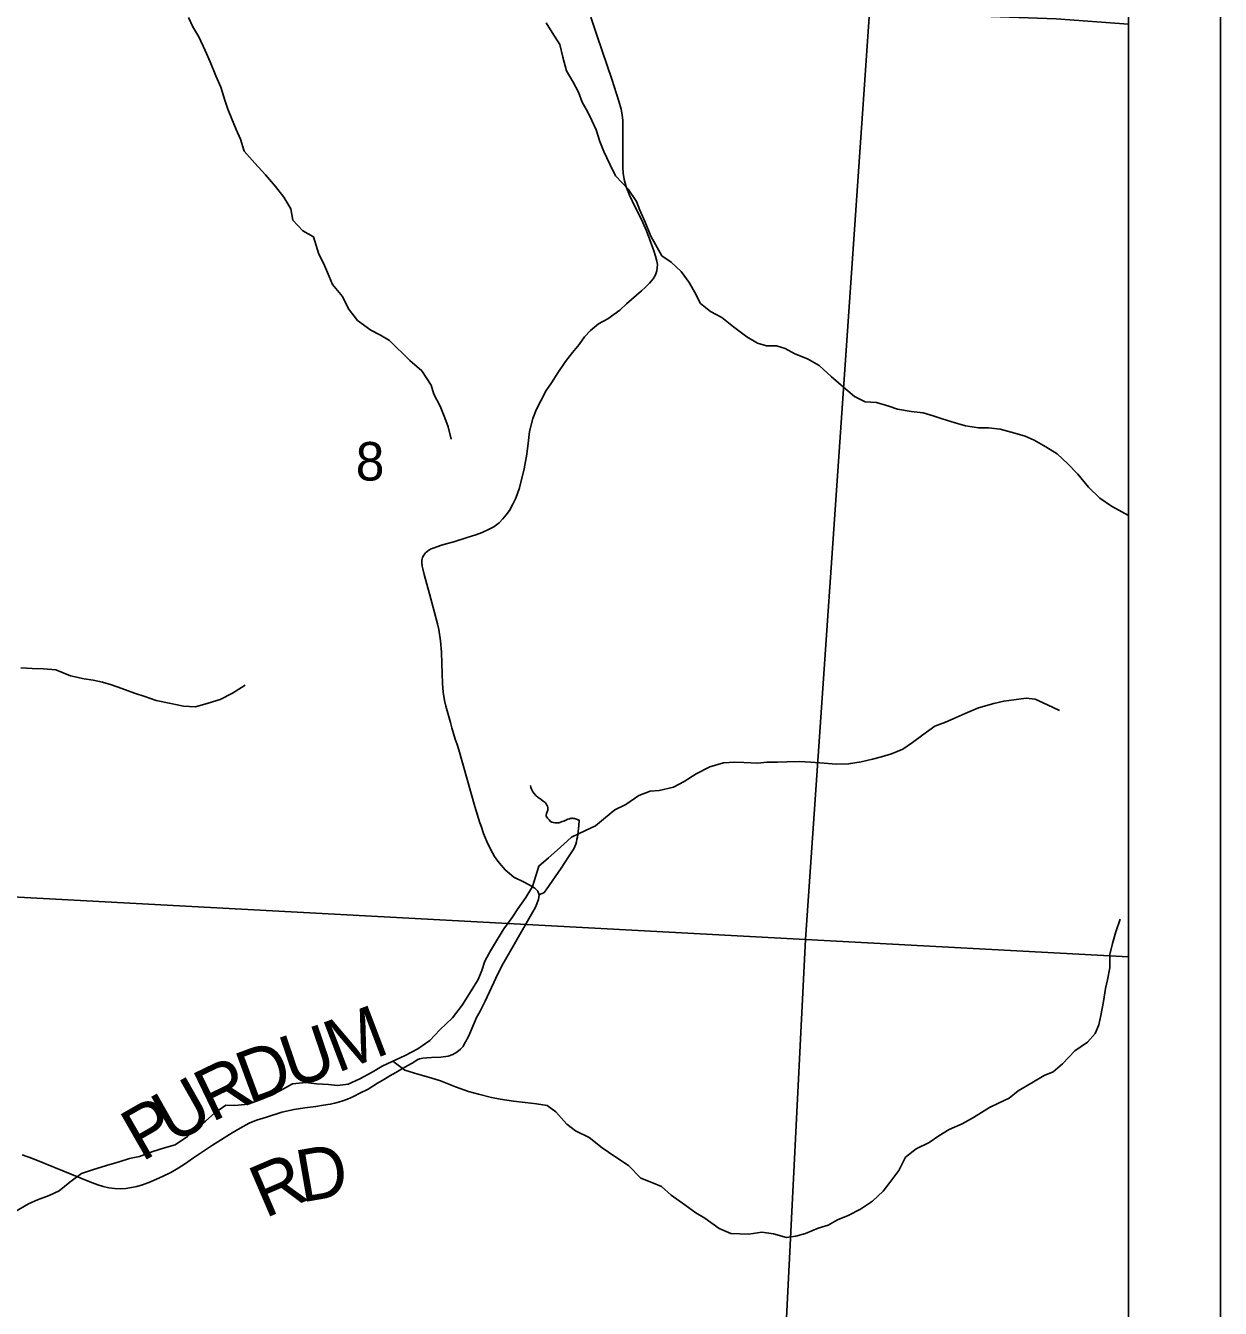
# Model space of a CAD drawing. Extents: x 39.8 to 73.8, y 13 to 35.
# Drawn here: x 47.463 to 48.763, y 28.456 to 29.851 of the extents above; entities that cross this region are included whole.
import ezdxf

# ---------------------------------------------------------------- set-up
doc = ezdxf.new("R2010")
doc.units = 0
for name, color, linetype in [('GM_X_Corporation', 7, 'Continuous'), ('GM_X_Minor_River', 7, 'Continuous'), ('GM_X_Section_Text', 7, 'Continuous'), ('GM_X_Township_Road', 7, 'Continuous'), ('GM_X_Township_Road_Text', 7, 'Continuous'), ('SH_Data', 7, 'Continuous')]:
    doc.layers.add(name, color=color, linetype=linetype)

msp = doc.modelspace()

# ---------------------------------------------------------------- linework, layer by layer
at = {"layer": 'GM_X_Corporation'}
msp.add_lwpolyline([(47.095, 27.8783), (47.5149, 27.8498), (47.5414, 27.8484), (48.663, 27.7809), (48.663, 33.865), (43.6158, 33.865)], dxfattribs=at)
for points in [[(47.3645, 29.9274), (47.3755, 29.9267), (47.6104, 29.9124), (48.0851, 29.8835), (48.3814, 29.8655), (48.3118, 28.8573), (47.3001, 28.9116)], [(48.663, 28.8384), (48.663, 29.8523), (48.5842, 29.8582), (48.3814, 29.8655), (48.3118, 28.8573)], [(47.3001, 28.9116), (48.3118, 28.8573), (48.2586, 27.803), (47.2222, 27.869), (47.3019, 28.7918)], [(48.663, 27.7774), (48.663, 28.8384), (48.3118, 28.8573), (48.2586, 27.803)]]:
    msp.add_lwpolyline(points, close=True, dxfattribs=at)
at = {"layer": 'GM_X_Minor_River'}
for p, q in [((47.6403, 29.8596), (47.6453, 29.8494)), ((47.6453, 29.8494), (47.6518, 29.8388)), ((47.6518, 29.8388), (47.6587, 29.824)), ((47.6587, 29.824), (47.664, 29.8115)), ((47.664, 29.8115), (47.6701, 29.7964)), ((47.6701, 29.7964), (47.6755, 29.7839)), ((47.6755, 29.7839), (47.6801, 29.7698)), ((47.6801, 29.7698), (47.6832, 29.76)), ((47.6832, 29.76), (47.6874, 29.7501)), ((47.6874, 29.7501), (47.6924, 29.738)), ((47.6924, 29.738), (47.697, 29.7274)), ((47.697, 29.7274), (47.7012, 29.7145)), ((47.7012, 29.7145), (47.7126, 29.7013)), ((47.7126, 29.7013), (47.7244, 29.6888)), ((47.7244, 29.6888), (47.735, 29.6759)), ((47.735, 29.6759), (47.7442, 29.6642)), ((47.7442, 29.6642), (47.7518, 29.6517)), ((47.7518, 29.6517), (47.7538, 29.6392)), ((47.7538, 29.6392), (47.7648, 29.6279)), ((47.7648, 29.6279), (47.7763, 29.6212)), ((47.7763, 29.6212), (47.7823, 29.6025)), ((48.1435, 29.622), (48.1554, 29.6006)), ((47.7823, 29.6025), (47.7873, 29.5927)), ((48.1554, 29.6006), (48.1657, 29.5935)), ((47.7873, 29.5927), (47.7916, 29.5825)), ((48.1657, 29.5935), (48.1764, 29.5837)), ((47.7916, 29.5825), (47.797, 29.5693)), ((48.1764, 29.5837), (48.1852, 29.5717)), ((48.1852, 29.5717), (48.191, 29.5615)), ((47.797, 29.5693), (47.8081, 29.5565)), ((47.8081, 29.5565), (47.8146, 29.5429)), ((48.191, 29.5615), (48.1975, 29.5487)), ((47.8146, 29.5429), (47.8242, 29.5301)), ((48.1975, 29.5487), (48.2082, 29.5401)), ((47.8242, 29.5301), (47.8387, 29.5196)), ((48.2082, 29.5401), (48.2207, 29.5334)), ((48.2207, 29.5334), (48.2333, 29.5232)), ((47.8387, 29.5196), (47.8493, 29.5144)), ((48.2333, 29.5232), (48.2478, 29.5124)), ((47.8493, 29.5144), (47.8592, 29.5085)), ((47.8592, 29.5085), (47.8813, 29.4867)), ((48.2478, 29.5124), (48.2595, 29.5057)), ((48.2595, 29.5057), (48.2694, 29.5027)), ((48.2694, 29.5027), (48.28, 29.5028)), ((48.28, 29.5028), (48.2895, 29.4999)), ((48.2895, 29.4999), (48.3001, 29.4939)), ((48.3001, 29.4939), (48.3138, 29.4887)), ((48.3138, 29.4887), (48.3267, 29.4813)), ((47.8813, 29.4867), (47.8943, 29.4754)), ((47.8943, 29.4754), (47.9043, 29.46)), ((48.3267, 29.4813), (48.3397, 29.4693)), ((47.9043, 29.46), (47.9074, 29.4502)), ((48.3397, 29.4693), (48.353, 29.4576)), ((47.9074, 29.4502), (47.9143, 29.437)), ((48.353, 29.4576), (48.3649, 29.4475)), ((48.3649, 29.4475), (48.3766, 29.4419)), ((47.9143, 29.437), (47.9193, 29.4245)), ((48.3766, 29.4419), (48.3888, 29.4409)), ((48.3888, 29.4409), (48.4024, 29.4372)), ((48.4024, 29.4372), (48.4119, 29.4339)), ((48.4119, 29.4339), (48.4267, 29.4314)), ((48.4267, 29.4314), (48.4396, 29.43)), ((47.9193, 29.4245), (47.9228, 29.4147)), ((48.4396, 29.43), (48.4506, 29.4267)), ((48.4506, 29.4267), (48.4604, 29.4234)), ((48.4604, 29.4234), (48.4745, 29.4189)), ((48.4745, 29.4189), (48.4858, 29.4156)), ((47.9228, 29.4147), (47.9263, 29.4011)), ((48.4858, 29.4156), (48.4999, 29.4135)), ((48.4999, 29.4135), (48.5108, 29.4136)), ((48.5108, 29.4136), (48.5233, 29.4122)), ((48.5233, 29.4122), (48.5393, 29.4078)), ((48.5393, 29.4078), (48.5506, 29.4045)), ((48.5506, 29.4045), (48.5605, 29.4)), ((48.5605, 29.4), (48.5731, 29.3929)), ((48.5731, 29.3929), (48.5856, 29.3851)), ((48.5856, 29.3851), (48.5971, 29.3742)), ((48.5971, 29.3742), (48.6081, 29.3633)), ((48.6081, 29.3633), (48.6196, 29.349)), ((48.6196, 29.349), (48.6318, 29.337)), ((48.6318, 29.337), (48.6444, 29.3284)), ((48.6444, 29.3284), (48.6558, 29.3221)), ((48.6558, 29.3221), (48.663, 29.3182)), ((47.4582, 29.1524), (47.4703, 29.1517)), ((47.4703, 29.1517), (47.4828, 29.1515)), ((47.4828, 29.1515), (47.496, 29.1504)), ((47.496, 29.1504), (47.512, 29.1438)), ((47.512, 29.1438), (47.5268, 29.1405)), ((47.5268, 29.1405), (47.5366, 29.1391)), ((47.5366, 29.1391), (47.5469, 29.1369)), ((47.5469, 29.1369), (47.5567, 29.1339)), ((47.5567, 29.1339), (47.5681, 29.1299)), ((47.5681, 29.1299), (47.5818, 29.1251)), ((47.5818, 29.1251), (47.5928, 29.1214)), ((47.6749, 29.118), (47.6885, 29.1249)), ((47.6885, 29.1249), (47.702, 29.1338)), ((47.5928, 29.1214), (47.6053, 29.117)), ((47.6053, 29.117), (47.6212, 29.1137)), ((47.6212, 29.1137), (47.6349, 29.1108)), ((47.6349, 29.1108), (47.6481, 29.1101)), ((47.6481, 29.1101), (47.6617, 29.1141)), ((47.6617, 29.1141), (47.6749, 29.118)), ((48.6492, 28.8654), (48.654, 28.8794)), ((48.6455, 28.8528), (48.6492, 28.8654)), ((48.6429, 28.8407), (48.6455, 28.8528)), ((48.6427, 28.8263), (48.6429, 28.8407)), ((48.6402, 28.8134), (48.6427, 28.8263)), ((48.6358, 28.7898), (48.638, 28.8039)), ((48.638, 28.8039), (48.6402, 28.8134)), ((48.6329, 28.7743), (48.6358, 28.7898)), ((48.6267, 28.7549), (48.6307, 28.7644)), ((48.6307, 28.7644), (48.6329, 28.7743)), ((48.6184, 28.7454), (48.6267, 28.7549)), ((48.5914, 28.722), (48.6045, 28.7361)), ((48.6045, 28.7361), (48.6184, 28.7454)), ((47.8627, 28.7248), (47.8759, 28.7151)), ((48.5812, 28.7132), (48.5914, 28.722)), ((47.8759, 28.7151), (47.89, 28.7107)), ((47.89, 28.7107), (47.904, 28.7066)), ((47.904, 28.7066), (47.9146, 28.7033)), ((48.5579, 28.7012), (48.5714, 28.7093)), ((48.5714, 28.7093), (48.5812, 28.7132)), ((47.9146, 28.7033), (47.931, 28.697)), ((47.931, 28.697), (47.945, 28.6918)), ((47.945, 28.6918), (47.956, 28.6889)), ((48.5331, 28.6847), (48.5432, 28.6924)), ((48.5432, 28.6924), (48.5579, 28.7012)), ((47.956, 28.6889), (47.97, 28.6853)), ((47.97, 28.6853), (47.9795, 28.6834)), ((47.9795, 28.6834), (47.9939, 28.6813)), ((47.9939, 28.6813), (48.0068, 28.6799)), ((48.0068, 28.6799), (48.0189, 28.6785)), ((48.0189, 28.6785), (48.0307, 28.6767)), ((48.512, 28.6743), (48.5218, 28.6793)), ((48.5218, 28.6793), (48.5331, 28.6847)), ((48.0307, 28.6767), (48.0402, 28.6696)), ((48.0402, 28.6696), (48.052, 28.6564)), ((48.4943, 28.6635), (48.512, 28.6743)), ((48.052, 28.6564), (48.0615, 28.649)), ((48.4566, 28.6435), (48.4679, 28.6504)), ((48.4679, 28.6504), (48.4822, 28.6566)), ((48.4822, 28.6566), (48.4943, 28.6635)), ((48.0615, 28.649), (48.0764, 28.6419)), ((48.0764, 28.6419), (48.0905, 28.6306)), ((48.4321, 28.6296), (48.4461, 28.6365)), ((48.4461, 28.6365), (48.4566, 28.6435)), ((48.0905, 28.6306), (48.1042, 28.6213)), ((48.4205, 28.6204), (48.4321, 28.6296)), ((48.1042, 28.6213), (48.119, 28.6112)), ((48.119, 28.6112), (48.1324, 28.5977)), ((48.4131, 28.6059), (48.4205, 28.6204)), ((48.1324, 28.5977), (48.1445, 28.5929)), ((48.4033, 28.5929), (48.4131, 28.6059)), ((48.1445, 28.5929), (48.1552, 28.5884)), ((48.1552, 28.5884), (48.1655, 28.579)), ((48.3846, 28.5727), (48.3962, 28.5834)), ((48.3962, 28.5834), (48.4033, 28.5929)), ((48.1655, 28.579), (48.1803, 28.5686)), ((48.1803, 28.5686), (48.1925, 28.56)), ((48.3714, 28.5639), (48.3846, 28.5727)), ((48.1925, 28.56), (48.202, 28.554)), ((48.202, 28.554), (48.2176, 28.5428)), ((48.3364, 28.5465), (48.3465, 28.5523)), ((48.3465, 28.5523), (48.3582, 28.5569)), ((48.3582, 28.5569), (48.3714, 28.5639)), ((48.2176, 28.5428), (48.2305, 28.5376)), ((48.2502, 28.5366), (48.2642, 28.539)), ((48.2642, 28.539), (48.2767, 28.5369)), ((48.3115, 28.5375), (48.3254, 28.5434)), ((48.3254, 28.5434), (48.3364, 28.5465)), ((48.2305, 28.5376), (48.2404, 28.5369)), ((48.2404, 28.5369), (48.2502, 28.5366)), ((48.2767, 28.5369), (48.2911, 28.5332)), ((48.2911, 28.5332), (48.3013, 28.5344)), ((48.3013, 28.5344), (48.3115, 28.5375))]:
    msp.add_line(p, q, dxfattribs=at)
for points in [[(48.0296, 29.854), (48.0361, 29.8434), (48.0445, 29.8302), (48.0476, 29.8165), (48.0518, 29.8018), (48.0591, 29.7893), (48.0648, 29.7787), (48.0686, 29.7677), (48.0747, 29.7574), (48.0793, 29.7476), (48.0839, 29.7374), (48.0881, 29.7249), (48.0924, 29.7139), (48.0988, 29.7002), (48.105, 29.6874), (48.1187, 29.673), (48.1278, 29.6597), (48.1316, 29.6503), (48.1374, 29.637), (48.1435, 29.622)], [(48.3721, 29.0504), (48.3846, 29.0532), (48.3944, 29.0556), (48.4053, 29.0591), (48.4174, 29.0641), (48.4279, 29.0714), (48.4392, 29.0798), (48.4524, 29.0891), (48.4641, 29.0933), (48.4757, 29.0987), (48.4855, 29.103), (48.4999, 29.1092), (48.5165, 29.1139), (48.5274, 29.1163), (48.5384, 29.1179), (48.5516, 29.1195), (48.5614, 29.1185), (48.5751, 29.1122), (48.588, 29.1062)], [(47.4516, 28.5608), (47.4663, 28.5696), (47.4761, 28.5739), (47.4889, 28.5789), (47.4998, 28.5839), (47.5115, 28.5931), (47.5239, 28.6027), (47.536, 28.6066), (47.5514, 28.6113), (47.565, 28.6152), (47.5763, 28.6191), (47.5873, 28.6211), (47.6016, 28.6266), (47.6145, 28.6305), (47.6258, 28.634), (47.6393, 28.6428), (47.6491, 28.6516), (47.6588, 28.6597), (47.669, 28.6685), (47.681, 28.6769), (47.6909, 28.6766), (47.7052, 28.6779), (47.7184, 28.6826), (47.729, 28.6872), (47.7407, 28.693), (47.7535, 28.7), (47.7682, 28.7016), (47.7796, 28.7002), (47.7928, 28.6996), (47.8027, 28.6985), (47.814, 28.6997), (47.8268, 28.7055), (47.8404, 28.7129), (47.8513, 28.7194), (47.8619, 28.7244), (47.8762, 28.731), (47.8901, 28.7383), (47.9029, 28.7472), (47.9138, 28.759), (47.9277, 28.772), (47.9381, 28.7858), (47.9478, 28.8014), (47.9557, 28.8136), (47.9594, 28.8235), (47.9627, 28.8334), (47.969, 28.8448), (47.9765, 28.8574), (47.9836, 28.8688), (47.9926, 28.881), (47.9989, 28.8905), (48.0075, 28.9027), (48.0146, 28.9149), (48.0183, 28.9263), (48.0216, 28.937), (48.0321, 28.9458), (48.0449, 28.9573), (48.0573, 28.9684), (48.0723, 28.9757), (48.0833, 28.9807), (48.0941, 28.9899), (48.1043, 28.998), (48.1163, 29.0041), (48.1303, 29.0138), (48.1427, 29.0184), (48.1525, 29.0193), (48.168, 29.0228), (48.1797, 29.029), (48.1929, 29.0371), (48.2076, 29.0448), (48.2223, 29.0491), (48.2348, 29.0499), (48.2446, 29.0497), (48.2597, 29.049), (48.2696, 29.0499), (48.2813, 29.05), (48.2915, 29.0505), (48.3051, 29.0506), (48.3176, 29.0499), (48.332, 29.0489), (48.3449, 29.0479), (48.3585, 29.048), (48.3721, 29.0504)]]:
    msp.add_lwpolyline(points, dxfattribs=at)
at = {"layer": 'GM_X_Township_Road'}
for points in [[(47.4597, 28.6229), (47.4708, 28.6189), (47.4842, 28.6134), (47.533, 28.5937), (47.5417, 28.5903), (47.5476, 28.5885), (47.5537, 28.5872), (47.5598, 28.5864), (47.566, 28.5861), (47.5722, 28.5865), (47.5784, 28.5874), (47.5844, 28.5887), (47.5903, 28.5904), (47.599, 28.5937), (47.613, 28.5997), (47.6213, 28.6039), (47.6293, 28.6086), (47.6371, 28.6137), (47.6447, 28.619), (47.6664, 28.6334), (47.6881, 28.6468), (47.6965, 28.6518), (47.7065, 28.6574), (47.7143, 28.6607), (47.7252, 28.664), (47.7421, 28.6694), (47.7553, 28.6723), (47.767, 28.6742), (47.7789, 28.6757), (47.7872, 28.6769), (47.7947, 28.678), (47.7998, 28.6792), (47.8073, 28.6814), (47.8136, 28.6836), (47.8198, 28.6865), (47.8269, 28.6899), (47.8358, 28.6944), (47.8459, 28.7008), (47.8537, 28.7053), (47.8595, 28.7089), (47.8659, 28.7124), (47.8734, 28.7169), (47.879, 28.72), (47.8839, 28.7228), (47.8866, 28.7245), (47.8891, 28.7261), (47.8918, 28.7274), (47.8955, 28.7281), (47.8996, 28.7286), (47.9047, 28.7289), (47.915, 28.7293), (47.9229, 28.7304), (47.9279, 28.7319), (47.9325, 28.7345), (47.9365, 28.7379), (47.9391, 28.7409), (47.9409, 28.744), (47.9424, 28.7468), (47.9435, 28.7492), (47.9449, 28.7518), (47.9522, 28.7686), (47.9535, 28.7715), (47.9578, 28.7791), (47.9631, 28.7901), (47.9747, 28.815), (47.9815, 28.8286), (47.9923, 28.8474), (48.0178, 28.8922), (48.0212, 28.9005), (48.0221, 28.9057), (48.0205, 28.9097), (48.0172, 28.9128), (48.0136, 28.9151), (48.0103, 28.9169), (48.0065, 28.919), (47.9944, 28.925), (47.9895, 28.9288), (47.985, 28.9329), (47.9808, 28.9375), (47.977, 28.9423), (47.9735, 28.9474), (47.969, 28.9555), (47.965, 28.9638), (47.9615, 28.9723), (47.9587, 28.9804), (47.9574, 28.984), (47.9521, 29.0019), (47.9346, 29.0633), (47.9327, 29.0693), (47.9306, 29.0749), (47.927, 29.0872), (47.9255, 29.0932), (47.9203, 29.111), (47.919, 29.1171), (47.9176, 29.1262), (47.9169, 29.1355), (47.9162, 29.1572), (47.9157, 29.1697), (47.9146, 29.182), (47.9127, 29.1943), (47.9115, 29.2004), (47.9067, 29.2183), (47.9025, 29.2331), (47.8969, 29.2541), (47.8953, 29.2601), (47.8946, 29.2631), (47.8944, 29.2662), (47.8944, 29.2694), (47.8946, 29.271), (47.8951, 29.2726), (47.8963, 29.275), (47.8974, 29.2765), (47.8983, 29.2777), (47.9019, 29.2806), (47.9046, 29.282), (47.9076, 29.2831), (47.9145, 29.2857), (47.9206, 29.2874), (47.929, 29.2897), (47.9438, 29.2943), (47.9529, 29.2971), (47.9598, 29.2996), (47.9677, 29.3032), (47.9725, 29.3057), (47.9783, 29.3103), (47.9824, 29.3146), (47.9862, 29.3189), (47.9898, 29.3238), (47.9933, 29.3304), (47.9964, 29.337), (48.0004, 29.3482), (48.0058, 29.3688), (48.0086, 29.385), (48.0102, 29.3997), (48.0116, 29.4097), (48.0149, 29.4237), (48.019, 29.4338), (48.0236, 29.4427), (48.0294, 29.454), (48.0353, 29.4626), (48.0421, 29.4732), (48.0505, 29.4857), (48.0581, 29.4954), (48.0653, 29.5043), (48.0711, 29.5124), (48.0777, 29.5193), (48.0864, 29.5266), (48.0968, 29.532), (48.1097, 29.5414), (48.1171, 29.5482), (48.1225, 29.5532), (48.1332, 29.5625), (48.1377, 29.5666), (48.142, 29.5709), (48.1441, 29.5732), (48.146, 29.5756), (48.1476, 29.5783), (48.1489, 29.5811), (48.1499, 29.5842), (48.1504, 29.5875), (48.1505, 29.591), (48.1501, 29.5946), (48.1484, 29.6003), (48.1467, 29.606), (48.1423, 29.618), (48.1387, 29.6278), (48.1331, 29.6402), (48.1265, 29.6535), (48.1202, 29.6667), (48.1166, 29.6756), (48.1143, 29.6835), (48.1133, 29.6906), (48.1128, 29.6967), (48.1128, 29.7046), (48.1129, 29.7322), (48.1131, 29.7416), (48.1129, 29.7478), (48.1122, 29.7539), (48.111, 29.7599), (48.1085, 29.7688), (48.1009, 29.7925), (48.085, 29.8395), (48.0782, 29.86)], [(48.0314, 28.9994), (48.0312, 29.0008), (48.031, 29.0021), (48.0304, 29.0033), (48.0294, 29.0047), (48.0283, 29.006), (48.0264, 29.0075), (48.024, 29.0092), (48.0209, 29.0114), (48.0184, 29.0137), (48.0164, 29.016), (48.015, 29.0178), (48.0138, 29.0199), (48.013, 29.0223), (48.0125, 29.0247)], [(48.0221, 28.9057), (48.0274, 28.9083), (48.0297, 28.911), (48.0457, 28.9346), (48.054, 28.9469), (48.0595, 28.9557), (48.0607, 28.9583), (48.0618, 28.9608), (48.0624, 28.9635), (48.0631, 28.9664), (48.0635, 28.9685), (48.0644, 28.9741), (48.0649, 28.9777), (48.0652, 28.9812), (48.0654, 28.9869), (48.0626, 28.9879), (48.0613, 28.9883), (48.0603, 28.9886), (48.0595, 28.9887), (48.0588, 28.9888), (48.058, 28.9889), (48.0574, 28.9889), (48.0566, 28.9888), (48.0558, 28.9887), (48.0549, 28.9884), (48.0532, 28.9878), (48.0486, 28.9859), (48.047, 28.9853), (48.0446, 28.9844), (48.0433, 28.9841), (48.042, 28.9839), (48.0405, 28.9839), (48.039, 28.984), (48.0375, 28.9842), (48.0358, 28.9847), (48.0344, 28.9856), (48.0327, 28.9873), (48.031, 28.989), (48.0303, 28.99), (48.0297, 28.9912), (48.0297, 28.9925), (48.0301, 28.9942), (48.0312, 28.9979), (48.0314, 28.9994)]]:
    msp.add_lwpolyline(points, dxfattribs=at)
at = {"layer": 'SH_Data'}
for p, q in [((48.763, 33.965), (48.763, 26.965)), ((48.663, 33.865), (48.663, 27.065))]:
    msp.add_line(p, q, dxfattribs=at)

# ---------------------------------------------------------------- texts
at = {"layer": 'GM_X_Section_Text'}
msp.add_text('8', height=0.0419, rotation=0, dxfattribs=at).set_placement((47.8224, 29.3562))
at = {"layer": 'GM_X_Township_Road_Text'}
for s, rotation, p in [('M', 20.8873, (47.8022, 28.7117)), ('U', 18.7379, (47.7527, 28.6949)), ('D', 20.3267, (47.7062, 28.6777)), ('R', 25.7587, (47.6655, 28.6579)), ('U', 29.5217, (47.6228, 28.6338)), ('P', 29.7455, (47.5896, 28.6148)), ('D', 9.8516, (47.7632, 28.571)), ('R', 23.1945, (47.7236, 28.5536))]:
    msp.add_text(s, height=0.0568, rotation=rotation, dxfattribs=at).set_placement(p)

doc.saveas('drawing.dxf')
